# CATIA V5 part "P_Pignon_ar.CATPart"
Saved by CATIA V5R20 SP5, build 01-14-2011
Part number: Pignon_ar
Bounding box of the stored display mesh (mm): x -5 to 5, y 177.727 to 187.727, z 140 to 150
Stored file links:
  U:\2A\CFAO\dossier sans titre\P_Pignon_ar.CATPart
  U:\2A\CFAO\dossier sans titre\Gouvernail.CATProduct
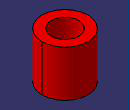
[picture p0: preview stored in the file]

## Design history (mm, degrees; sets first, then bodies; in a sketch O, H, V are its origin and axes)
Set1
  Point1: linked copy from another document
Body1 (main body)
  Sketch1 on xy-plane, origin (0, 0, 0), H (1, 0, 0), V (0, 1, 0)
    circle A1 centre (0, 182.7273) radius 5
    point P1 (0, 182.7273)
    reference projected point E1 (0, 182.7273) from Point1
    radius A1 = 5
    coincidence: P1 E1
  Pad1: profile Sketch1, direction (0, 0, 1), length 150, opposite side length -140
  Sketch2 on end face of Pad1, origin (0, 182.7273, 150), H (1, 0, 0), V (0, 1, 0)
    point P1 (0, 0)
  Hole1: placed by Sketch2, at (0, 182.7273, 150) direction (0, 0, -1), diameter 6, through (limit type 3)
